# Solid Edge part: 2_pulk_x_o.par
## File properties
Author: Romil
Template: iso part.par
Last saved by: Romil
Revision: 34
Application: Solid Edge
Accuracy: 0.990
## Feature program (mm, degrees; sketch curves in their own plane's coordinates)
sketch for "unnamed Protrusion 1" plane through (0, 0, 0) normal (1, 0, 0) x-axis (0, 1, 0)
  arc centre (0, 0) radius 2.35 from (2.181, 0.875) to (2.181, -0.875) cw
  arc centre (0, 0) radius 2.35 from (-0.875, 2.181) to (0.875, 2.181) cw
  arc centre (0, 0) radius 2.35 from (-2.181, -0.875) to (-2.181, 0.875) cw
extrude "unnamed Protrusion 1" add finite 7.8 along -normal
fillet "Round_8" radius 0.2  Radii2 = 0.2 mm
sketch for "ExtrudedCutout_2" plane through (-7.8, 0, 0) normal (-1, 0, 0) x-axis (0, 0, 1)
extrude "ExtrudedCutout_2" cut finite 0.1 along -normal
sketch used by "ExtrudedProtrusion_2" plane through (0, 0, 0) normal (1, 0, 0) x-axis (0, 1, 0)
extrude "ExtrudedProtrusion_2" add finite 0.9 along +normal
sketch for "ExtrudedProtrusion_3" plane through (0, 0, 0) normal (1, 0, 0) x-axis (0, 1, 0)
extrude "ExtrudedProtrusion_3" add finite 7.8 along +normal
sketch for "ExtrudedProtrusion_4" plane through (7.8, 0, 0) normal (1, 0, 0) x-axis (0, -1, 0)
extrude "ExtrudedProtrusion_4" add finite 0.8 along -normal
sketch for "unnamed Cutout 1" plane through (7.8, 0, 0) normal (1, 0, 0) x-axis (0, -1, 0)
extrude "unnamed Cutout 1" cut to key point along -normal
fillet "Round_9" radius 0.3
sketch for "ExtrudedCutout_4" plane through (7.8, 0, 0) normal (1, 0, 0) x-axis (0, 0, -1)
extrude "ExtrudedCutout_4" cut finite 3 along -normal
fillet "Round_10" radius 0.4
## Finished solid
Body 1: solid body, 55 faces, 136 edges, 84 vertices.
  Faces by surface: cylinder 24, plane 19, torus 12
  Edges by curve: line 60, circle 48, intersection 28
Bounding box of the edges (mm; curved faces can reach further): 15.600 x 6.200 x 6.200, from (-7.8, -3.1, -3.1) to (7.8, 3.1, 3.1).
Cylindrical faces by radius (mm): R0.1 x4, R0.2 x9, R0.4 x2, R1.7 x1, R2.35 x5, R2.5976 x2, R3.1 x1
Toroidal faces (ring radius, tube radius in mm): R0.3 r0.2 x4, R1.8 r0.55 x4, R2.2976 r0.3 x4
Planar faces by outward normal: +x 4, +y 2, +z 4, -x 3, -y 2, -z 4
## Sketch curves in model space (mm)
circle centre (0, 0, 0) radius 1.4
circle centre (0, 0, 0) radius 2.35
circle centre (0, 0, 0) radius 3.1
line (0, 4.3566, -0.4) -> (0, 4.3566, 0.4)
line (0, 4.3566, 0.4) -> (0, -4.3566, 0.4)
line (0, -4.3566, 0.4) -> (0, -4.3566, -0.4)
line (0, -4.3566, -0.4) -> (0, 4.3566, -0.4)
arc centre (0, -0.975, -0.975) radius 0.1 from (0, -0.975, -0.875) through (0, -0.9023, -0.9064) to (0, -0.875, -0.975)
line (0, -0.875, -0.975) -> (0, -0.875, -2.181)
arc centre (0, 0, 0) radius 2.35 from (0, 0.875, -2.181) through (0, 0, -2.35) to (0, -0.875, -2.181)
line (0, 0.875, -2.181) -> (0, 0.875, -0.975)
arc centre (0, 0.975, -0.975) radius 0.1 from (0, 0.875, -0.975) through (0, 0.9064, -0.9023) to (0, 0.975, -0.875)
line (0, 0.975, -0.875) -> (0, 2.181, -0.875)
arc centre (0, 0, 0) radius 2.35 from (0, 2.181, 0.875) through (0, 2.35, 0) to (0, 2.181, -0.875)
line (0, 2.181, 0.875) -> (0, 0.975, 0.875)
arc centre (0, 0.975, 0.975) radius 0.1 from (0, 0.975, 0.875) through (0, 0.9023, 0.9064) to (0, 0.875, 0.975)
line (0, 0.875, 0.975) -> (0, 0.875, 2.181)
arc centre (0, 0, 0) radius 2.35 from (0, -0.875, 2.181) through (0, 0, 2.35) to (0, 0.875, 2.181)
line (0, -0.875, 2.181) -> (0, -0.875, 0.975)
arc centre (0, -0.975, 0.975) radius 0.1 from (0, -0.875, 0.975) through (0, -0.9064, 0.9023) to (0, -0.975, 0.875)
line (0, -0.975, 0.875) -> (0, -2.181, 0.875)
arc centre (0, 0, 0) radius 2.35 from (0, -2.181, -0.875) through (0, -2.35, 0) to (0, -2.181, 0.875)
line (0, -2.181, -0.875) -> (0, -0.975, -0.875)
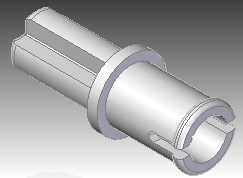
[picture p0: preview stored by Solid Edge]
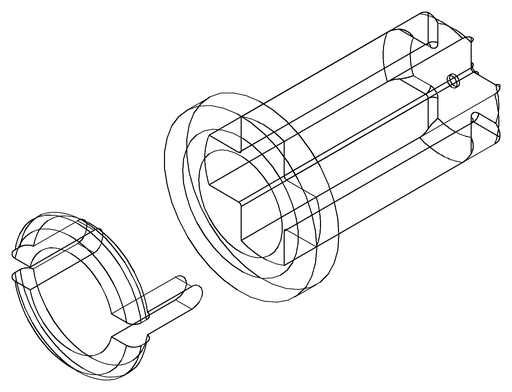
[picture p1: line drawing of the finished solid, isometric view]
